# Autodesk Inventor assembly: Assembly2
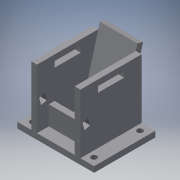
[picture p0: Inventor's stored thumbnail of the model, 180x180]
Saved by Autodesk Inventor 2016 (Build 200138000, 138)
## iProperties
Created: 2017-06
Part Number: Assembly2
Document SubType Name: Assembly
Designer: laboratorioesan
Author: laboratorioesan
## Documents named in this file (5)
- C:\Users\laboratorioesan\Desktop\Proyecto final\FAROS\Assembly2.iam
- C:\Users\laboratorioesan\Desktop\Proyecto final\FAROS\frontal_delantero.ipt
- C:\Users\laboratorioesan\Desktop\Proyecto final\FAROS\Part4.ipt
- C:\Users\laboratorioesan\Desktop\Proyecto final\FAROS\Part5.ipt
- C:\Users\laboratorioesan\Desktop\Proyecto final\FAROS\Part6.ipt
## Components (6 placed, 4 different names)
1. frontal_delantero:1 — Flush:1, Mate:1, Flush:3, Mate:4
2. Part4:1 — Flush:1, Flush:2, Mate:3, Flush:5
3. Part5:1 — Flush:2, Mate:2
4. Part4:2 — Mate:1, Flush:3, Mate:2, Flush:4
5. Part5:2 — Mate:3, Flush:4, Mate:4
6. Part6:1 — Flush:5
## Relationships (9: Flush 5, Mate 4)
- Flush:1: frontal_delantero:1 ↔ Part4:1
- Flush:2: Part4:1 ↔ Part5:1
- Mate:1: frontal_delantero:1 ↔ Part4:2
- Flush:3: frontal_delantero:1 ↔ Part4:2
- Mate:2: Part5:1 ↔ Part4:2
- Mate:3: Part4:1 ↔ Part5:2
- Flush:4: Part4:2 ↔ Part5:2
- Mate:4: frontal_delantero:1 ↔ Part5:2
- Flush:5: Part4:1 ↔ Part6:1
